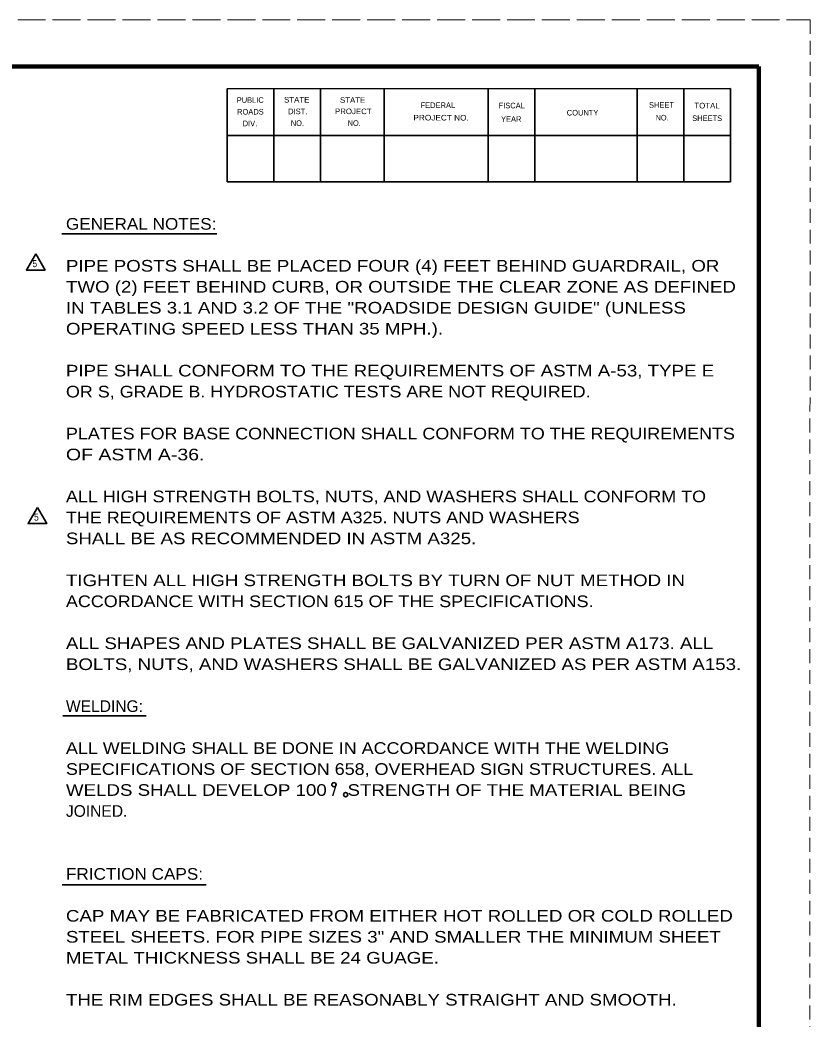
# Model space of a CAD drawing. Extents: x -209 to 471, y -242 to 199.
# Drawn here: x 301.8 to 471.4, y -15.9 to 198.5 of the extents above; entities that cross this region are included whole.
import ezdxf
from ezdxf.enums import TextEntityAlignment as Align

# ---------------------------------------------------------------- set-up
doc = ezdxf.new("R2010")
doc.units = 0
doc.linetypes.add('LONG_DASHED', pattern=[7.5, 6, -1.5])
doc.linetypes.add('MEDIUM_DASHED', pattern=[4.5, 3, -1.5])
doc.layers.add('1', color=7, linetype='Continuous', lineweight=53)
doc.layers.add('61', color=7, linetype='Continuous', lineweight=35)

msp = doc.modelspace()

# ---------------------------------------------------------------- linework, layer by layer
at = {"layer": '1', "linetype": 'MEDIUM_DASHED', "lineweight": 13}
msp.add_line((471.374, 198.515), (471.354, -241.505), dxfattribs=at)
at = {"layer": '1', "lineweight": 35}
for p, q in [((310.857, 152.624), (344.05, 152.624)), ((311.034, 49.213), (328.95, 49.213)), ((310.875, 12.93), (341.79, 12.93))]:
    msp.add_line(p, q, dxfattribs=at)
for points in [[(305.219, 148.316), (303.219, 144.852), (307.219, 144.852)], [(305.571, 93.912), (303.571, 90.448), (307.571, 90.448)]]:
    msp.add_lwpolyline(points, close=True, dxfattribs=at)
for centre in [(369.206, 34.411), (371.728, 32.266)]:
    msp.add_circle(centre, 0.455, dxfattribs=at)
at = {"layer": '61', "linetype": 'LONG_DASHED', "lineweight": 13}
msp.add_line((-208.646, 198.515), (471.374, 198.515), dxfattribs=at)
at = {"layer": '61', "lineweight": 158}
msp.add_line((460.394, 188.515), (460.414, -231.525), dxfattribs=at)
at = {"layer": '61'}
for p, q in [((356.314, 183.755), (356.314, 163.755)), ((366.314, 183.755), (366.314, 163.755)), ((379.994, 183.755), (379.994, 163.755)), ((402.314, 183.755), (402.314, 163.755)), ((412.314, 183.755), (412.314, 163.755)), ((434.294, 183.775), (434.294, 163.775)), ((444.294, 183.775), (444.294, 163.775)), ((454.314, 173.735), (346.294, 173.755))]:
    msp.add_line(p, q, dxfattribs=at)
at = {"layer": '61', "lineweight": 158}
msp.add_lwpolyline([(460.394, 188.515), (-178.646, 188.515), (-178.646, -231.505)], dxfattribs=at)
at = {"layer": '61'}
for points in [[(454.294, 183.775), (346.314, 183.755), (346.314, 163.755)], [(454.294, 183.775), (454.294, 163.775), (346.314, 163.755)]]:
    msp.add_lwpolyline(points, dxfattribs=at)

# ---------------------------------------------------------------- texts
at = {"layer": '1'}
for s, width, p in [('GENERAL NOTES:', 1.1, (311.706, 153.511)), ('PIPE POSTS SHALL BE PLACED FOUR (4) FEET BEHIND GUARDRAIL, OR', 1.2, (311.706, 144.511)), ('TWO (2) FEET BEHIND CURB, OR OUTSIDE THE CLEAR ZONE AS DEFINED', 1.2, (311.706, 140.011)), ('IN TABLES 3.1 AND 3.2 OF THE "ROADSIDE DESIGN GUIDE" (UNLESS', 1.2, (311.706, 135.511)), ('OPERATING SPEED LESS THAN 35 MPH.).', 1.2, (311.706, 131.011)), ('PIPE SHALL CONFORM TO THE REQUIREMENTS OF ASTM A-53, TYPE E', 1.2, (311.706, 122.011)), ('OR S, GRADE B. HYDROSTATIC TESTS ARE NOT REQUIRED.', 1.15, (311.706, 117.511)), ('PLATES FOR BASE CONNECTION SHALL CONFORM TO THE REQUIREMENTS', 1.15, (311.706, 108.511)), ('OF ASTM A-36.', 1.25, (311.706, 104.011)), ('ALL HIGH STRENGTH BOLTS, NUTS, AND WASHERS SHALL CONFORM TO', 1.15, (311.706, 95.011)), ('THE REQUIREMENTS OF ASTM A325. NUTS AND WASHERS', 1.15, (311.706, 90.511)), ('SHALL BE AS RECOMMENDED IN ASTM A325.', 1.2, (311.706, 86.011)), ('TIGHTEN ALL HIGH STRENGTH BOLTS BY TURN OF NUT METHOD IN', 1.2, (311.706, 77.011)), ('ACCORDANCE WITH SECTION 615 OF THE SPECIFICATIONS.', 1.15, (311.706, 72.511)), ('ALL SHAPES AND PLATES SHALL BE GALVANIZED PER ASTM A173. ALL', 1.2, (311.706, 63.511)), ('BOLTS, NUTS, AND WASHERS SHALL BE GALVANIZED AS PER ASTM A153.', 1.2, (311.706, 59.011)), ('ALL WELDING SHALL BE DONE IN ACCORDANCE WITH THE WELDING', 1.15, (311.706, 41.011)), ('SPECIFICATIONS OF SECTION 658, OVERHEAD SIGN STRUCTURES. ALL', 1.15, (311.706, 36.511)), ('WELDS SHALL DEVELOP 100 /  STRENGTH OF THE MATERIAL BEING', 1.2, (311.706, 32.011)), ('FRICTION CAPS:', 1.1, (311.706, 14.011)), ('CAP MAY BE FABRICATED FROM EITHER HOT ROLLED OR COLD ROLLED', 1.2, (311.706, 5.011)), ('STEEL SHEETS. FOR PIPE SIZES 3" AND SMALLER THE MINIMUM SHEET', 1.2, (311.706, 0.511)), ('METAL THICKNESS SHALL BE 24 GUAGE.', 1.2, (311.706, -3.989)), ('THE RIM EDGES SHALL BE REASONABLY STRAIGHT AND SMOOTH.', 1.2, (311.706, -12.989))]:
    msp.add_text(s, height=2.5, dxfattribs=dict(at, width=width)).set_placement(p)
at = {"layer": '1', "width": 0.9}
for p in [(305.026, 145.473), (305.378, 91.068)]:
    msp.add_text('5', height=1.5, dxfattribs=at).set_placement(p, align=Align.CENTER)
at = {"layer": '1'}
for s, p in [('WELDING:', (311.706, 50.011)), ('JOINED.', (311.706, 27.511))]:
    msp.add_text(s, height=2.5, dxfattribs=at).set_placement(p)
at = {"layer": '61'}
for s, rotation, p in [('PUBLIC', 0.033, (348.354, 180.735)), ('FEDERAL', 0.007, (387.814, 179.615)), ('FISCAL', 359.942, (404.554, 179.555)), ('SHEET', 0.059, (436.814, 179.675)), ('ROADS', 0.124, (348.434, 178.215)), ('DIST.', 0.056, (359.394, 178.295)), ('COUNTY', 0.069, (419.174, 178.015)), ('SHEETS', 359.959, (446.094, 176.835)), ('DIV.', 359.932, (349.634, 175.715)), ('YEAR', 0.105, (405.074, 176.655))]:
    msp.add_text(s, height=1.201, rotation=rotation, dxfattribs=at).set_placement(p)
for s, rotation, width, p in [('STATE', 0.059, 1.05, (358.514, 180.795)), ('STATE', 0.059, 1.05, (370.514, 180.735)), ('TOTAL', 359.926, 1.05, (446.554, 179.535)), ('PROJECT', 359.908, 1.05, (369.434, 178.315)), ('PROJECT NO.', 359.922, 1.1, (386.274, 176.955)), ('NO.', 359.852, 0.95, (438.234, 176.955)), ('NO.', 359.852, 0.95, (359.974, 175.775)), ('NO.', 0.225, 0.95, (372.174, 175.775))]:
    msp.add_text(s, height=1.201, rotation=rotation, dxfattribs=dict(at, width=width)).set_placement(p)

doc.saveas('drawing.dxf')
